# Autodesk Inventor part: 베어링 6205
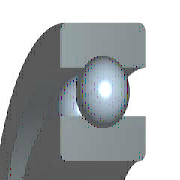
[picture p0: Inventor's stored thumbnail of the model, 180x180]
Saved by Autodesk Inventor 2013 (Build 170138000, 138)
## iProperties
Created: 2015-10
Part Number: 베어링 6205
Material: 강, 연강
Description: 깊은 그루브 볼 베어링
Document SubType Name: Modeling
Standard: KS B 2023
Designer: mdu
Standards Organization: KS
Language: ko-KR
Size Designation: 6205 - 25 x 52 x 15
Categories: <MemberInstance><Categories><Category DisplayName="샤프트 부품" InternalName="7f7aeb1f-a693-4053-b835-cee3144e0d98" Mnemonic="SHFT"><Category DisplayName="베어링" Inter
Density: 7.86 g/cm^3
Mass: 129.543 g
Surface Area: 107.326 cm^2
Volume: 16.4813 cm^3
IsCustomPart: 1
Author: mdu
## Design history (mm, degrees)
sketch "스케치" dims "d0" = 7.02 (= -0.26 x WD + 0.26 x BD)
  geometry: L1 (3.99, 19.25)-(11.01, 19.25); L2 (7.5, 19.25)-(7.5, 15.74); L3 (7.5, 19.25)-(7.5, 22.76); L4 (4.892, 16.901)-(0, 16.901); L5 (0, 12.5)-(15, 12.5); L6 (4.892, 21.599)-(0, 21.599); L7 (0, 26)-(15, 26); L8 (15, 12.5)-(15, 16.901); L9 (10.108, 16.901)-(15, 16.901); L10 (10.108, 21.599)-(15, 21.599); L11 (15, 26)-(15, 21.599); L12 (-1.4, 0)-(8.4, 0) reference; L13 (0, -0.3)-(0, 5.3) reference
  constraints: 22 end point, 4 point on line, 2 collinear, 2 perpendicular, 2 symmetric about line, 1 midpoint, 1 parallel, 14 other
  dimensions: "d9" = 25 diameter of L5 L12 (= WD); "d11" = 52 diameter of L7 L12 (= BD); "d12" = 15 distance between parallel lines of L8 L13 (= KB); "d13" = 33.802 diameter of L9 L12 (= 0.326 x BD + 0.674 x WD)
revolve "본체" stored, may be unused: angle "d6" = 90 deg
revolve "볼" stored, may be unused: angle "d7" = 90 deg
pattern_circular "IDS_ARRAYBALL[SIMPL:T]" dims angle "d3" = 360 deg
body "Solid1"
fillet "모깎기1" dims "d1" = 1 (= KRS)
other parameters: "WD" = 25 [user parameter; used in 5 equation terms], "BD" = 52 [user parameter; used in 5 equation terms], "KB" = 15 [user parameter; used in 1 equation term], "KRS" = 1 [user parameter; used in 1 equation term], "d4" = 0, "d5" = 0, "d8" = 0, "d14" = 0, "d15" = 0, "BBA" = 0 [user parameter], "BC0" = 7800000 [user parameter], "BC" = 1.4e+07 [user parameter], "BR" = 26 (= 0.5 x BD) [user parameter], "WR" = 12.5 (= 0.5 x WD) [user parameter]
